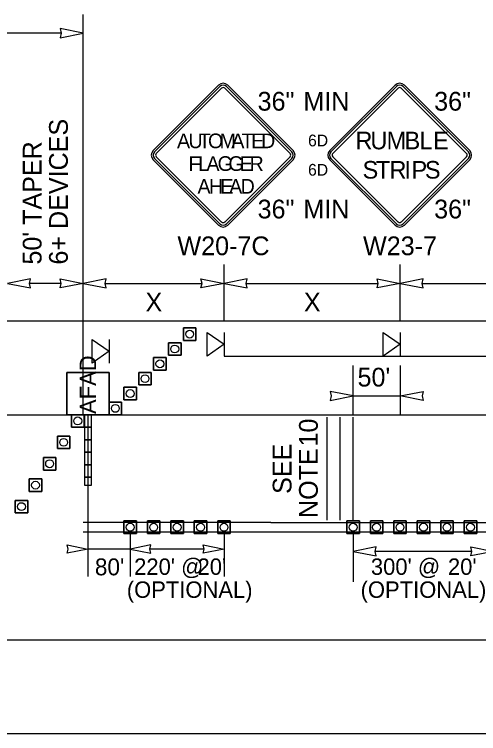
# Model space of a CAD drawing. Extents: x 99999.1 to 100095.7, y 99995 to 100010.7.
# Drawn here: x 100051.18 to 100053.158, y 100005.732 to 100008.799 of the extents above; entities that cross this region are included whole.
import ezdxf

# ---------------------------------------------------------------- set-up
doc = ezdxf.new("R2010")
doc.units = 0
for name, color, linetype in [('RD_ED_ShoulderPavedEdge', 7, 'Continuous'), ('RD_MK_LineDblYellowCenter', 7, 'Continuous'), ('RD_MK_LineEdgeWhite', 7, 'Continuous'), ('RD_MK_LineNoPass', 7, 'Continuous'), ('RD_MK_LineSkipCenter', 7, 'Continuous'), ('TR_SN_ConstructionSigns', 7, 'Continuous'), ('TR_WZ_AFAD', 7, 'Continuous'), ('TR_WZ_PortableSignMountBlk-Org', 7, 'Continuous'), ('TR_WZ_PortableSignMountBlk-Wht', 7, 'Continuous'), ('TR_WZ_TrafficCone', 7, 'Continuous'), ('TR_WZ_WorkZoneDetails', 7, 'Continuous'), ('TR_WZ_WorkZoneTextCurrent', 7, 'Continuous')]:
    doc.layers.add(name, color=color, linetype=linetype)

msp = doc.modelspace()

# ---------------------------------------------------------------- linework, layer by layer
at = {"layer": 'RD_ED_ShoulderPavedEdge'}
for p, q in [((100040.1076, 100007.4923), (100055.6424, 100007.4923)), ((100040.1076, 100005.7323), (100055.6424, 100005.7323))]:
    msp.add_line(p, q, dxfattribs=at)
at = {"layer": 'RD_MK_LineDblYellowCenter'}
for p, q in [((100052.2733, 100006.6323), (100055.6631, 100006.6323)), ((100052.2733, 100006.5923), (100055.6218, 100006.5923))]:
    msp.add_line(p, q, dxfattribs=at)
at = {"layer": 'RD_MK_LineEdgeWhite'}
for p, q in [((100040.1076, 100007.0923), (100055.6424, 100007.0923)), ((100040.1076, 100006.1323), (100055.6424, 100006.1323))]:
    msp.add_line(p, q, dxfattribs=at)
at = {"layer": 'RD_MK_LineNoPass'}
msp.add_line((100051.4733, 100006.5923), (100052.2733, 100006.5923), dxfattribs=at)
at = {"layer": 'RD_MK_LineSkipCenter'}
msp.add_lwpolyline([(100052.2733, 100006.6323), (100051.4733, 100006.6323)], dxfattribs=at)
at = {"layer": 'TR_SN_ConstructionSigns'}
for p, q in [((100052.0497, 100008.4972), (100051.7713, 100008.2188)), ((100052.0552, 100008.4917), (100051.7768, 100008.2132)), ((100051.7845, 100008.2055), (100052.063, 100008.4839)), ((100052.0762, 100008.4839), (100052.3546, 100008.2055)), ((100052.3624, 100008.2132), (100052.0839, 100008.4917)), ((100052.3679, 100008.2188), (100052.0895, 100008.4972)), ((100052.8019, 100008.4972), (100052.5235, 100008.2188)), ((100052.8075, 100008.4917), (100052.529, 100008.2132)), ((100052.5368, 100008.2055), (100052.8152, 100008.4839)), ((100052.8285, 100008.4839), (100053.1069, 100008.2055)), ((100053.1146, 100008.2132), (100052.8362, 100008.4917)), ((100053.1201, 100008.2188), (100052.8417, 100008.4972)), ((100051.7713, 100008.179), (100052.0497, 100007.9006)), ((100051.7768, 100008.1845), (100052.0552, 100007.9061)), ((100052.063, 100007.9138), (100051.7845, 100008.1923)), ((100052.3546, 100008.1923), (100052.0762, 100007.9138)), ((100052.0839, 100007.9061), (100052.3624, 100008.1845)), ((100052.0895, 100007.9006), (100052.3679, 100008.179)), ((100052.5235, 100008.179), (100052.8019, 100007.9006)), ((100052.529, 100008.1845), (100052.8075, 100007.9061)), ((100052.8152, 100007.9138), (100052.5368, 100008.1923)), ((100053.1069, 100008.1923), (100052.8285, 100007.9138)), ((100052.8362, 100007.9061), (100053.1146, 100008.1845)), ((100052.8417, 100007.9006), (100053.1201, 100008.179))]:
    msp.add_line(p, q, dxfattribs=at)
for centre, radius, start, end in [((100052.0696, 100008.4773), 0.0281, 45, 135), ((100052.0696, 100008.4773), 0.0203, 45, 135), ((100052.0696, 100008.4773), 0.00937, 45, 135), ((100052.8218, 100008.4773), 0.0281, 45, 135), ((100052.8218, 100008.4773), 0.0203, 45, 135), ((100052.8218, 100008.4773), 0.00937, 45, 135), ((100051.7912, 100008.1989), 0.0281, 135, 225), ((100051.7912, 100008.1989), 0.0203, 135, 225), ((100051.7912, 100008.1989), 0.00937, 135, 225), ((100052.348, 100008.1989), 0.00937, 315, 45), ((100052.348, 100008.1989), 0.0203, 315, 45), ((100052.348, 100008.1989), 0.0281, 315, 45), ((100052.5434, 100008.1989), 0.0281, 135, 225), ((100052.5434, 100008.1989), 0.0203, 135, 225), ((100052.5434, 100008.1989), 0.00937, 135, 225), ((100053.1003, 100008.1989), 0.00937, 315, 45), ((100053.1003, 100008.1989), 0.0203, 315, 45), ((100053.1003, 100008.1989), 0.0281, 315, 45), ((100052.0696, 100007.9205), 0.0281, 225, 315), ((100052.0696, 100007.9205), 0.0203, 225, 315), ((100052.0696, 100007.9205), 0.00937, 225, 315), ((100052.8218, 100007.9205), 0.0281, 225, 315), ((100052.8218, 100007.9205), 0.0203, 225, 315), ((100052.8218, 100007.9205), 0.00937, 225, 315)]:
    msp.add_arc(centre, radius, start, end, dxfattribs=at)
at = {"layer": 'TR_WZ_AFAD'}
for p, q in [((100051.4033, 100007.0923), (100051.4033, 100007.2723)), ((100051.4033, 100007.2723), (100051.5833, 100007.2723)), ((100051.5833, 100007.2723), (100051.4033, 100007.2723)), ((100051.4033, 100007.2723), (100051.4033, 100007.0923)), ((100051.5833, 100007.2723), (100051.5833, 100007.0923)), ((100051.5833, 100007.0923), (100051.5833, 100007.2723)), ((100051.5833, 100007.0923), (100051.4033, 100007.0923)), ((100051.5, 100007.0923), (100051.4933, 100007.0923)), ((100051.5, 100007.0923), (100051.5833, 100007.0923)), ((100051.5083, 100007.0923), (100051.5, 100007.0923)), ((100051.5083, 100007.039), (100051.5083, 100007.0923)), ((100051.4783, 100007.039), (100051.4783, 100006.9857)), ((100051.5083, 100006.9857), (100051.5083, 100007.039)), ((100051.4783, 100006.9857), (100051.4783, 100006.9323)), ((100051.4783, 100006.9857), (100051.4933, 100006.9857)), ((100051.4933, 100006.9857), (100051.5083, 100006.9857)), ((100051.5083, 100006.9323), (100051.5083, 100006.9857)), ((100051.4933, 100006.9323), (100051.4783, 100006.9323)), ((100051.4783, 100006.9323), (100051.4783, 100006.879)), ((100051.5083, 100006.9323), (100051.4933, 100006.9323)), ((100051.5083, 100006.879), (100051.5083, 100006.9323)), ((100051.4783, 100006.879), (100051.4783, 100006.8257)), ((100051.4783, 100006.879), (100051.4933, 100006.879)), ((100051.4933, 100006.879), (100051.5083, 100006.879)), ((100051.5083, 100006.8257), (100051.5083, 100006.879)), ((100051.4933, 100006.8257), (100051.4783, 100006.8257)), ((100051.4783, 100006.8257), (100051.4783, 100006.7923)), ((100051.5083, 100006.8257), (100051.4933, 100006.8257))]:
    msp.add_line(p, q, dxfattribs=at)
for points in [[(100051.4033, 100007.0923), (100051.4867, 100007.0923), (100051.5, 100007.0923)], [(100051.4933, 100007.0923), (100051.4867, 100007.0923), (100051.4783, 100007.0923), (100051.4783, 100007.039)], [(100051.4783, 100007.0923), (100051.4783, 100006.7923), (100051.5083, 100006.7923), (100051.5083, 100007.0923)], [(100051.4783, 100007.039), (100051.4933, 100007.039), (100051.5083, 100007.039)], [(100051.5083, 100007.039), (100051.4933, 100007.039), (100051.4783, 100007.039)], [(100051.5083, 100006.9857), (100051.4933, 100006.9857), (100051.4783, 100006.9857)], [(100051.4783, 100006.9323), (100051.4933, 100006.9323), (100051.5083, 100006.9323)], [(100051.5083, 100006.879), (100051.4933, 100006.879), (100051.4783, 100006.879)], [(100051.4783, 100006.8257), (100051.4933, 100006.8257), (100051.5083, 100006.8257)], [(100051.4783, 100006.7923), (100051.5083, 100006.7923), (100051.5083, 100006.8257)]]:
    msp.add_lwpolyline(points, dxfattribs=at)
at = {"layer": 'TR_WZ_PortableSignMountBlk-Org'}
for p, q in [((100052.0733, 100007.4422), (100052.0733, 100007.3422)), ((100052.8233, 100007.4422), (100052.8233, 100007.3422))]:
    msp.add_line(p, q, dxfattribs=at)
for points in [[(100052.0733, 100007.3923), (100052.0015, 100007.3422), (100052.0015, 100007.4422)], [(100052.8233, 100007.3923), (100052.7515, 100007.3422), (100052.7515, 100007.4422)]]:
    msp.add_lwpolyline(points, close=True, dxfattribs=at)
at = {"layer": 'TR_WZ_PortableSignMountBlk-Wht'}
msp.add_line((100051.5833, 100007.4123), (100051.5833, 100007.3123), dxfattribs=at)
msp.add_lwpolyline([(100051.5833, 100007.3624), (100051.5115, 100007.3123), (100051.5115, 100007.4123)], close=True, dxfattribs=at)
at = {"layer": 'TR_WZ_TrafficCone'}
for points in [[(100051.9533, 100007.4623), (100051.9, 100007.4623), (100051.9, 100007.409), (100051.9533, 100007.409), (100051.9533, 100007.4623)], [(100051.9533, 100007.409), (100051.9, 100007.409), (100051.9, 100007.4623), (100051.9533, 100007.4623), (100051.9533, 100007.409)], [(100051.89, 100007.399), (100051.8367, 100007.399), (100051.8367, 100007.3457), (100051.89, 100007.3457), (100051.89, 100007.399)], [(100051.89, 100007.3457), (100051.8367, 100007.3457), (100051.8367, 100007.399), (100051.89, 100007.399), (100051.89, 100007.3457)], [(100051.8267, 100007.3357), (100051.7733, 100007.3357), (100051.7733, 100007.2823), (100051.8267, 100007.2823), (100051.8267, 100007.3357)], [(100051.8267, 100007.2823), (100051.7733, 100007.2823), (100051.7733, 100007.3357), (100051.8267, 100007.3357), (100051.8267, 100007.2823)], [(100051.7633, 100007.219), (100051.71, 100007.219), (100051.71, 100007.2723), (100051.7633, 100007.2723), (100051.7633, 100007.219)], [(100051.7633, 100007.2723), (100051.71, 100007.2723), (100051.71, 100007.219), (100051.7633, 100007.219), (100051.7633, 100007.2723)], [(100051.7, 100007.1557), (100051.6467, 100007.1557), (100051.6467, 100007.209), (100051.7, 100007.209), (100051.7, 100007.1557)], [(100051.7, 100007.209), (100051.6467, 100007.209), (100051.6467, 100007.1557), (100051.7, 100007.1557), (100051.7, 100007.209)], [(100051.6367, 100007.0923), (100051.5833, 100007.0923), (100051.5833, 100007.1457), (100051.6367, 100007.1457), (100051.6367, 100007.0923)], [(100051.6367, 100007.1457), (100051.5833, 100007.1457), (100051.5833, 100007.0923), (100051.6367, 100007.0923), (100051.6367, 100007.1457)], [(100051.4766, 100007.0923), (100051.4233, 100007.0923), (100051.4233, 100007.039), (100051.4766, 100007.039), (100051.4766, 100007.0923)], [(100051.4766, 100007.039), (100051.4233, 100007.039), (100051.4233, 100007.0923), (100051.4766, 100007.0923), (100051.4766, 100007.039)], [(100051.4166, 100007.001), (100051.3633, 100007.001), (100051.3633, 100006.9477), (100051.4166, 100006.9477), (100051.4166, 100007.001)], [(100051.4166, 100006.9477), (100051.3633, 100006.9477), (100051.3633, 100007.001), (100051.4166, 100007.001), (100051.4166, 100006.9477)], [(100051.3566, 100006.9097), (100051.3033, 100006.9097), (100051.3033, 100006.8563), (100051.3566, 100006.8563), (100051.3566, 100006.9097)], [(100051.3566, 100006.8563), (100051.3033, 100006.8563), (100051.3033, 100006.9097), (100051.3566, 100006.9097), (100051.3566, 100006.8563)], [(100051.2966, 100006.8183), (100051.2433, 100006.8183), (100051.2433, 100006.765), (100051.2966, 100006.765), (100051.2966, 100006.8183)], [(100051.2966, 100006.765), (100051.2433, 100006.765), (100051.2433, 100006.8183), (100051.2966, 100006.8183), (100051.2966, 100006.765)], [(100051.2366, 100006.727), (100051.1833, 100006.727), (100051.1833, 100006.6737), (100051.2366, 100006.6737), (100051.2366, 100006.727)], [(100051.2366, 100006.6737), (100051.1833, 100006.6737), (100051.1833, 100006.727), (100051.2366, 100006.727), (100051.2366, 100006.6737)], [(100051.7, 100006.639), (100051.6467, 100006.639), (100051.6467, 100006.5857), (100051.7, 100006.5857), (100051.7, 100006.639)], [(100051.7, 100006.5857), (100051.6467, 100006.5857), (100051.6467, 100006.639), (100051.7, 100006.639), (100051.7, 100006.5857)], [(100051.8, 100006.639), (100051.7467, 100006.639), (100051.7467, 100006.5857), (100051.8, 100006.5857), (100051.8, 100006.639)], [(100051.8, 100006.5857), (100051.7467, 100006.5857), (100051.7467, 100006.639), (100051.8, 100006.639), (100051.8, 100006.5857)], [(100051.9, 100006.639), (100051.8467, 100006.639), (100051.8467, 100006.5857), (100051.9, 100006.5857), (100051.9, 100006.639)], [(100051.9, 100006.5857), (100051.8467, 100006.5857), (100051.8467, 100006.639), (100051.9, 100006.639), (100051.9, 100006.5857)], [(100052, 100006.639), (100051.9467, 100006.639), (100051.9467, 100006.5857), (100052, 100006.5857), (100052, 100006.639)], [(100052, 100006.5857), (100051.9467, 100006.5857), (100051.9467, 100006.639), (100052, 100006.639), (100052, 100006.5857)], [(100052.1, 100006.639), (100052.0467, 100006.639), (100052.0467, 100006.5857), (100052.1, 100006.5857), (100052.1, 100006.639)], [(100052.1, 100006.5857), (100052.0467, 100006.5857), (100052.0467, 100006.639), (100052.1, 100006.639), (100052.1, 100006.5857)], [(100052.65, 100006.5857), (100052.5967, 100006.5857), (100052.5967, 100006.639), (100052.65, 100006.639), (100052.65, 100006.5857)], [(100052.65, 100006.639), (100052.5967, 100006.639), (100052.5967, 100006.5857), (100052.65, 100006.5857), (100052.65, 100006.639)], [(100052.75, 100006.5857), (100052.6967, 100006.5857), (100052.6967, 100006.639), (100052.75, 100006.639), (100052.75, 100006.5857)], [(100052.75, 100006.639), (100052.6967, 100006.639), (100052.6967, 100006.5857), (100052.75, 100006.5857), (100052.75, 100006.639)], [(100052.85, 100006.5857), (100052.7967, 100006.5857), (100052.7967, 100006.639), (100052.85, 100006.639), (100052.85, 100006.5857)], [(100052.85, 100006.639), (100052.7967, 100006.639), (100052.7967, 100006.5857), (100052.85, 100006.5857), (100052.85, 100006.639)], [(100052.95, 100006.5857), (100052.8967, 100006.5857), (100052.8967, 100006.639), (100052.95, 100006.639), (100052.95, 100006.5857)], [(100052.95, 100006.639), (100052.8967, 100006.639), (100052.8967, 100006.5857), (100052.95, 100006.5857), (100052.95, 100006.639)], [(100053.05, 100006.5857), (100052.9967, 100006.5857), (100052.9967, 100006.639), (100053.05, 100006.639), (100053.05, 100006.5857)], [(100053.05, 100006.639), (100052.9967, 100006.639), (100052.9967, 100006.5857), (100053.05, 100006.5857), (100053.05, 100006.639)], [(100053.15, 100006.5857), (100053.0967, 100006.5857), (100053.0967, 100006.639), (100053.15, 100006.639), (100053.15, 100006.5857)], [(100053.15, 100006.639), (100053.0967, 100006.639), (100053.0967, 100006.5857), (100053.15, 100006.5857), (100053.15, 100006.639)]]:
    msp.add_lwpolyline(points, dxfattribs=at)
for centre in [(100051.9267, 100007.4357), (100051.8633, 100007.3723), (100051.8, 100007.309), (100051.7367, 100007.2457), (100051.6733, 100007.1823), (100051.61, 100007.119), (100051.45, 100007.0657), (100051.39, 100006.9743), (100051.33, 100006.883), (100051.27, 100006.7917), (100051.21, 100006.7003), (100051.6733, 100006.6123), (100051.7733, 100006.6123), (100051.8733, 100006.6123), (100051.9733, 100006.6123), (100052.0733, 100006.6123), (100052.6233, 100006.6123), (100052.7233, 100006.6123), (100052.8233, 100006.6123), (100052.9233, 100006.6123), (100053.0233, 100006.6123), (100053.1233, 100006.6123)]:
    msp.add_circle(centre, 0.0167, dxfattribs=at)
at = {"layer": 'TR_WZ_WorkZoneDetails'}
for p, q in [((100051.4733, 100007.0923), (100051.4733, 100008.7991)), ((100051.3796, 100008.7191), (100044.3704, 100008.7191)), ((100052.0733, 100007.4923), (100052.0733, 100007.7323)), ((100052.8233, 100007.4923), (100052.8233, 100007.7323)), ((100051.3796, 100007.6523), (100051.2437, 100007.6523)), ((100051.5671, 100007.6523), (100051.9796, 100007.6523)), ((100052.1671, 100007.6523), (100052.7296, 100007.6523)), ((100052.9171, 100007.6523), (100053.4796, 100007.6523)), ((100052.0733, 100007.3422), (100055.1733, 100007.3422)), ((100052.6233, 100007.0923), (100052.6233, 100007.3023)), ((100052.8233, 100007.3023), (100052.8233, 100007.0923)), ((100052.6233, 100007.1723), (100052.8233, 100007.1723)), ((100051.4933, 100007.0923), (100051.4933, 100006.4023)), ((100052.5128, 100006.6423), (100052.5128, 100007.0823)), ((100052.5685, 100006.6423), (100052.5685, 100007.0823)), ((100052.6233, 100006.6423), (100052.6233, 100007.0823)), ((100051.6733, 100006.5857), (100051.6733, 100006.4023)), ((100052.0733, 100006.5857), (100052.0733, 100006.4023)), ((100052.6233, 100006.589), (100052.6233, 100006.379)), ((100051.6733, 100006.5193), (100051.4933, 100006.5193)), ((100051.989, 100006.5193), (100051.7577, 100006.5193)), ((100053.1296, 100006.509), (100052.7171, 100006.509))]:
    msp.add_line(p, q, dxfattribs=at)
for points in [[(100051.4733, 100008.7191), (100051.3751, 100008.7384), (100051.3796, 100008.7191), (100051.3751, 100008.6998)], [(100051.15, 100007.6523), (100051.2483, 100007.6331), (100051.2437, 100007.6523), (100051.2483, 100007.6716)], [(100051.4733, 100007.6523), (100051.3751, 100007.6331), (100051.3796, 100007.6523), (100051.3751, 100007.6716)], [(100051.4733, 100007.6523), (100051.5716, 100007.6331), (100051.5671, 100007.6523), (100051.5716, 100007.6716)], [(100052.0733, 100007.6523), (100051.9751, 100007.6331), (100051.9796, 100007.6523), (100051.9751, 100007.6716)], [(100052.0733, 100007.6523), (100052.1716, 100007.6331), (100052.1671, 100007.6523), (100052.1716, 100007.6716)], [(100052.8233, 100007.6523), (100052.7251, 100007.6331), (100052.7296, 100007.6523), (100052.7251, 100007.6716)], [(100052.8233, 100007.6523), (100052.9216, 100007.6331), (100052.9171, 100007.6523), (100052.9216, 100007.6716)], [(100052.6233, 100007.1723), (100052.5251, 100007.1916), (100052.5296, 100007.1723), (100052.5251, 100007.1531)], [(100052.8233, 100007.1723), (100052.9216, 100007.1916), (100052.9171, 100007.1723), (100052.9216, 100007.1531)], [(100051.4933, 100006.5193), (100051.4049, 100006.502), (100051.409, 100006.5193), (100051.4049, 100006.5367)], [(100051.6733, 100006.5193), (100051.7618, 100006.502), (100051.7577, 100006.5193), (100051.7618, 100006.5367)], [(100052.0733, 100006.5193), (100051.9849, 100006.502), (100051.989, 100006.5193), (100051.9849, 100006.5367)], [(100052.6233, 100006.509), (100052.7216, 100006.4897), (100052.7171, 100006.509), (100052.7216, 100006.5283)], [(100053.2233, 100006.509), (100053.1251, 100006.4897), (100053.1296, 100006.509), (100053.1251, 100006.5283)]]:
    msp.add_lwpolyline(points, close=True, dxfattribs=at)

# ---------------------------------------------------------------- texts
at = {"layer": 'TR_SN_ConstructionSigns'}
for s, p in [('36"', (100052.2163, 100008.3887)), ('MIN', (100052.4114, 100008.3887)), ('36"', (100052.9686, 100008.3887)), ('36"', (100052.2163, 100007.9291)), ('MIN', (100052.4114, 100007.9291)), ('36"', (100052.9686, 100007.9291)), ('W20-7C', (100051.8748, 100007.7723)), ('W23-7', (100052.6656, 100007.7723))]:
    msp.add_text(s, height=0.08, rotation=360, dxfattribs=at).set_placement(p)
for s, height, p in [('R', 0.075, (100052.6332, 100008.2239)), ('U', 0.075, (100052.697, 100008.2239)), ('M', 0.075, (100052.766, 100008.2239)), ('B', 0.075, (100052.8425, 100008.2239)), ('L', 0.075, (100052.9062, 100008.2239)), ('E', 0.075, (100052.964, 100008.2239)), ('A', 0.0625, (100051.873, 100008.2286)), ('U', 0.0625, (100051.9218, 100008.2286)), ('T', 0.0625, (100051.9655, 100008.2286)), ('O', 0.0625, (100052.0049, 100008.2286)), ('M', 0.0625, (100052.0543, 100008.2286)), ('A', 0.0625, (100052.1043, 100008.2286)), ('T', 0.0625, (100052.148, 100008.2286)), ('E', 0.0625, (100052.1886, 100008.2286)), ('D', 0.0625, (100052.2311, 100008.2286)), ('6D', 0.05, (100052.4313, 100008.2364)), ('F', 0.0625, (100051.9221, 100008.1317)), ('L', 0.0625, (100051.9627, 100008.1317)), ('A', 0.0625, (100051.9983, 100008.1317)), ('G', 0.0625, (100052.0458, 100008.1317)), ('G', 0.0625, (100052.0921, 100008.1317)), ('E', 0.0625, (100052.1396, 100008.1317)), ('R', 0.0625, (100052.1821, 100008.1317)), ('S', 0.075, (100052.6636, 100008.0989)), ('T', 0.075, (100052.7206, 100008.0989)), ('R', 0.075, (100052.7783, 100008.0989)), ('I', 0.075, (100052.8421, 100008.0989)), ('P', 0.075, (100052.8721, 100008.0989)), ('S', 0.075, (100052.9291, 100008.0989)), ('6D', 0.05, (100052.4313, 100008.1114)), ('A', 0.0625, (100051.9602, 100008.0348)), ('H', 0.0625, (100052.009, 100008.0348)), ('E', 0.0625, (100052.0577, 100008.0348)), ('A', 0.0625, (100052.0952, 100008.0348)), ('D', 0.0625, (100052.144, 100008.0348))]:
    msp.add_text(s, height=height, dxfattribs=at).set_placement(p)
at = {"layer": 'TR_WZ_AFAD'}
msp.add_text('AFAD', height=0.07, rotation=90, dxfattribs=at).set_placement((100051.5283, 100007.0953))
at = {"layer": 'TR_WZ_WorkZoneDetails'}
for s, p in [('10', (100052.4728, 100006.9566)), ('SEE', (100052.3608, 100006.7544)), ('NOTE', (100052.4728, 100006.6518))]:
    msp.add_text(s, height=0.08, rotation=90, dxfattribs=at).set_placement(p)
at = {"layer": 'TR_WZ_WorkZoneTextCurrent'}
for s, p in [('6+ DEVICES', (100051.4077, 100007.7323)), ("50' TAPER", (100051.2957, 100007.7323))]:
    msp.add_text(s, height=0.08, rotation=90, dxfattribs=at).set_placement(p)
for s, height, p in [('X', 0.08, (100051.7386, 100007.5323)), ('X', 0.08, (100052.4136, 100007.5323)), ("50'", 0.08, (100052.6421, 100007.2123)), ("80'", 0.072, (100051.5229, 100006.4073)), ("220' @", 0.07, (100051.6903, 100006.4093)), ("20'", 0.07, (100051.9604, 100006.4093)), ("300' @", 0.07, (100052.6991, 100006.4093)), ("20'", 0.07, (100053.0275, 100006.4093)), ('(OPTIONAL)', 0.07, (100051.659, 100006.3113)), ('(OPTIONAL)', 0.07, (100052.6553, 100006.3113))]:
    msp.add_text(s, height=height, dxfattribs=at).set_placement(p)

doc.saveas('drawing.dxf')
